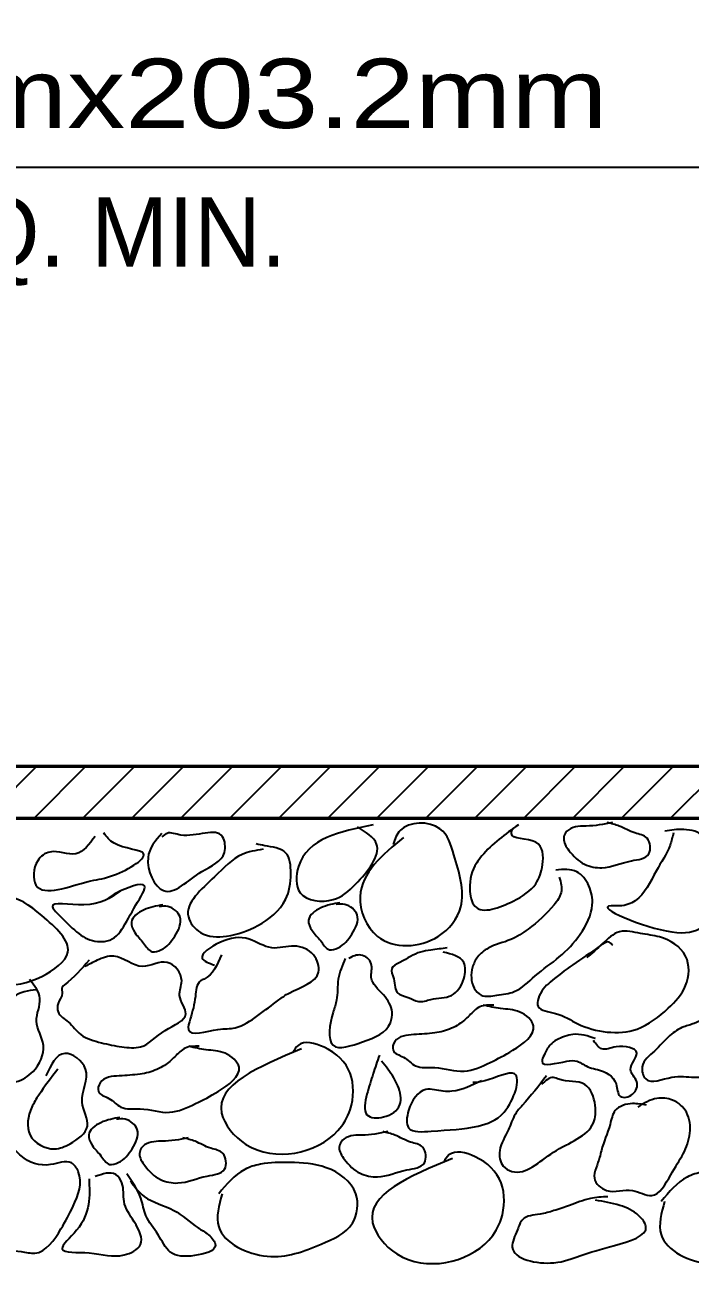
# Model space of a CAD drawing. Extents: x 442 to 1297, y -1132 to -588.
# Drawn here: x 1070.79 to 1093.84, y -929.08 to -885.89 of the extents above; entities that cross this region are included whole.
import ezdxf
from ezdxf.enums import TextEntityAlignment as Align

# ---------------------------------------------------------------- set-up
doc = ezdxf.new("R2010")
doc.units = 0
doc.header["$LTSCALE"] = 0.96
doc.layers.add('1', color=7, linetype='Continuous', lineweight=35)

msp = doc.modelspace()

# ---------------------------------------------------------------- linework, layer by layer
at = {"layer": '1'}
for p, q in [((1049.354, -890.8139), (1098.254, -890.8139)), ((1069.4082, -913.3617), (1071.2081, -911.5617)), ((1071.1053, -913.3617), (1072.9052, -911.5617)), ((1072.8024, -913.3617), (1074.6023, -911.5617)), ((1074.4994, -913.3617), (1076.2993, -911.5617)), ((1076.1964, -913.3617), (1077.9963, -911.5617)), ((1077.8934, -913.3617), (1079.6934, -911.5617)), ((1079.5904, -913.3617), (1081.3902, -911.5617)), ((1081.2874, -913.3617), (1083.0874, -911.5617)), ((1082.9844, -913.3617), (1084.7842, -911.5617)), ((1084.6815, -913.3617), (1086.4813, -911.5617)), ((1086.3784, -913.3617), (1088.1782, -911.5617)), ((1088.0755, -913.3617), (1089.8753, -911.5617)), ((1089.7724, -913.3617), (1091.5722, -911.5617)), ((1091.4695, -913.3617), (1093.2693, -911.5617)), ((1093.1664, -913.3617), (1094.9662, -911.5617))]:
    msp.add_line(p, q, dxfattribs=at)
at = {"layer": '1', "lineweight": 53}
msp.add_line((1049.354, -911.5617), (1098.254, -911.5617), dxfattribs=at)
msp.add_lwpolyline([(1047.554, -880.9617), (1047.554, -913.3617), (1100.054, -913.3617)], dxfattribs=at)
at = {"layer": '1'}
for points in [[(1073.2193, -913.9938), (1072.5576, -914.5953), (1071.6554, -914.5352), (1071.2344, -914.8359), (1071.1742, -915.678), (1072.9787, -915.5577), (1073.7606, -915.3773), (1074.9034, -914.5953), (1073.8809, -914.2344), (1073.52, -913.8735)], [(1075.5374, -913.889), (1075.0562, -914.731), (1075.5975, -915.8739), (1076.9208, -915.2122), (1077.7027, -914.5506), (1077.6426, -914.0093), (1076.199, -913.9491), (1075.7178, -913.889), (1075.5374, -914.0093)], [(1082.8568, -913.5979), (1080.2704, -915.0414), (1080.3305, -915.9437), (1081.4733, -916.1843), (1082.2553, -915.6429), (1082.9771, -914.2595), (1082.3154, -913.658)], [(1083.9092, -914.0298), (1082.4055, -916.0748), (1083.007, -917.4582), (1085.1122, -917.4582), (1085.8941, -916.4357), (1085.6535, -914.6312), (1085.1723, -913.729), (1083.7889, -913.7892), (1083.5483, -914.2703)], [(1087.8894, -913.589), (1086.6262, -914.6717), (1086.4458, -914.9123), (1086.2052, -915.8145), (1086.3856, -916.416), (1087.7089, -916.2356), (1088.4908, -915.6341), (1088.7314, -914.9724), (1088.4908, -914.1905), (1087.6488, -913.8898), (1087.7089, -913.7093)], [(1091.1468, -913.516), (1090.2445, -913.6363), (1090.1242, -913.6363), (1089.5227, -913.8769), (1089.4626, -914.0574), (1089.643, -914.4784), (1090.1844, -914.9596), (1090.7859, -915.0799), (1091.8084, -914.8393), (1092.4099, -914.5987), (1092.3497, -914.0574), (1091.9287, -913.8769), (1091.3873, -913.6363), (1090.9663, -913.516)], [(1093.2663, -913.8754), (1093.146, -914.2964), (1092.6648, -915.1986), (1091.943, -916.2212), (1091.4017, -916.4016), (1091.1009, -916.4016), (1093.2061, -917.3039), (1094.2888, -917.1234), (1094.8903, -916.4618), (1095.0707, -915.5595), (1094.5294, -914.8378), (1094.2888, -913.9957), (1093.6272, -913.7551), (1092.9655, -913.8152)], [(1079.0421, -914.438), (1078.3203, -914.6184), (1077.3579, -915.4003), (1076.4557, -916.7838), (1076.8767, -917.3251), (1077.7789, -917.4454), (1078.8616, -917.0845), (1079.824, -916.1823), (1080.0044, -915.28), (1079.824, -914.5583), (1079.1022, -914.3177), (1078.8015, -914.2575)], [(1089.3095, -915.4008), (1089.3697, -915.9421), (1089.1291, -916.3631), (1088.2268, -917.2052), (1087.6254, -917.5661), (1086.8434, -917.8669), (1086.4825, -918.1676), (1086.3021, -918.5285), (1086.3622, -919.2503), (1086.6028, -919.4909), (1087.1442, -919.4909), (1087.7456, -919.3706), (1088.4674, -918.8292), (1089.3095, -918.1676), (1090.0313, -917.3857), (1090.4523, -916.3631), (1090.332, -915.7015), (1089.911, -915.2203), (1089.1892, -915.1602)], [(1074.0914, -915.8887), (1072.8283, -916.3699), (1071.7456, -916.4301), (1072.0463, -916.791), (1073.3095, -917.633), (1073.5501, -917.633), (1074.6327, -916.3699), (1074.9335, -915.7083), (1073.9711, -915.9489), (1073.6704, -916.1293)], [(1069.6315, -916.6184), (1068.8496, -917.5807), (1068.9098, -918.3627), (1069.9323, -919.0845), (1071.3759, -918.8439), (1072.2781, -918.0018), (1071.3759, -916.7387), (1070.1729, -916.1372), (1069.391, -916.7988)], [(1075.5653, -916.3647), (1074.9037, -916.5452), (1074.4827, -916.9662), (1074.603, -917.3271), (1074.9037, -917.688), (1075.2044, -917.9888), (1075.5052, -917.9286), (1075.9864, -917.4474), (1076.1668, -916.7858), (1075.7458, -916.4249), (1075.445, -916.4249)], [(1081.7019, -916.2934), (1081.0403, -916.4739), (1080.6193, -916.8949), (1080.7396, -917.2558), (1081.0403, -917.6167), (1081.341, -917.9175), (1081.6418, -917.8573), (1082.123, -917.3761), (1082.3034, -916.7145), (1081.8824, -916.3536), (1081.5816, -916.3536)], [(1091.1597, -917.7784), (1091.0394, -917.6581), (1090.7386, -917.7784), (1089.7763, -918.44), (1088.9943, -919.0415), (1088.7537, -919.2821), (1088.5733, -919.8836), (1089.1748, -920.1242), (1089.9567, -920.4851), (1092.0018, -920.6655), (1093.0844, -919.9437), (1093.6859, -919.1618), (1093.6859, -918.1393), (1092.7837, -917.4776), (1092.1221, -917.3574), (1091.4003, -917.2972), (1090.7988, -917.7182), (1090.2574, -918.1994)], [(1077.5997, -918.0949), (1076.9982, -918.937), (1076.8779, -918.9972), (1076.6975, -919.5385), (1076.517, -920.3204), (1076.4569, -920.6813), (1077.4794, -920.6813), (1078.0809, -920.6212), (1078.8628, -920.2001), (1079.5846, -919.6588), (1079.9455, -919.4182), (1080.9681, -918.6964), (1080.7876, -918.0949), (1080.126, -917.7942), (1079.344, -917.8543), (1078.5621, -917.5536), (1077.5396, -917.6739), (1076.9381, -918.2152), (1077.3591, -918.4558)], [(1073.0116, -918.2858), (1072.1553, -919.1421), (1072.084, -919.2134), (1072.084, -919.4275), (1071.9413, -919.7843), (1071.9413, -920.0697), (1072.298, -920.4265), (1072.7262, -920.8546), (1073.4397, -921.14), (1074.1533, -921.2828), (1074.7955, -921.2828), (1075.6517, -920.7119), (1076.3653, -920.1411), (1076.1512, -919.4989), (1076.2226, -918.9994), (1075.7231, -918.3572), (1074.8668, -918.4999), (1073.8678, -918.1431), (1073.297, -918.2858), (1072.8689, -918.4999)], [(1081.8905, -918.2224), (1081.6499, -918.9441), (1081.5897, -919.6659), (1081.4694, -920.087), (1081.4694, -921.2298), (1082.492, -921.1095), (1083.4543, -920.4479), (1083.5145, -920.087), (1083.2137, -919.4855), (1082.7927, -918.884), (1082.7927, -918.4028), (1082.4318, -918.1021), (1082.0108, -918.2224)], [(1085.4274, -917.8577), (1084.8566, -917.9291), (1084.4998, -918.0004), (1083.7862, -918.3572), (1083.5008, -918.5713), (1083.5722, -918.928), (1083.7149, -919.4275), (1084.0717, -919.5702), (1084.4284, -919.7129), (1084.8566, -919.6416), (1085.5701, -919.4989), (1085.9982, -918.928), (1085.9982, -918.3572), (1085.2847, -918.0004)], [(1071.1916, -919.3087), (1070.4097, -919.5493), (1070.1691, -920.0305), (1069.9285, -920.7522), (1069.5676, -920.8725), (1069.3871, -921.5342), (1069.5676, -922.4364), (1070.4698, -922.4966), (1071.0713, -922.1357), (1071.4322, -921.2334), (1071.1916, -920.3913), (1071.3119, -919.6094), (1070.951, -918.9478)], [(1087.0359, -919.8369), (1086.5547, -919.8971), (1086.1939, -920.1978), (1085.833, -920.4986), (1085.2916, -920.7391), (1084.9909, -920.7993), (1084.2691, -920.8594), (1083.6075, -921.1), (1083.5473, -921.4008), (1083.9082, -921.6414), (1084.3292, -921.9421), (1084.9909, -922.0023), (1086.0134, -922.1226), (1086.9156, -921.8218), (1087.6976, -921.4008), (1088.4194, -920.5587), (1087.9382, -920.0775), (1087.2765, -919.9572), (1086.675, -919.8369)], [(1094.5878, -920.2892), (1094.287, -920.3494), (1093.9863, -920.4697), (1093.8059, -920.5298), (1093.6254, -920.59), (1093.1442, -920.8907), (1092.6029, -921.4321), (1092.1818, -921.9734), (1092.3021, -922.3945), (1093.2044, -922.3343), (1093.9863, -922.3343), (1094.9487, -922.214), (1095.6705, -921.8531), (1095.7306, -921.2516), (1095.4299, -920.6501), (1094.5878, -920.3494), (1094.287, -920.2291)], [(1080.3754, -921.3539), (1077.6085, -923.5794), (1078.4506, -924.662), (1081.6385, -924.1809), (1082.0595, -923.4591), (1082.0595, -922.1959), (1081.1573, -921.2937), (1080.2551, -921.2336), (1080.0746, -921.4742)], [(1090.565, -920.9973), (1089.7801, -920.8546), (1089.4947, -920.926), (1088.9952, -921.2114), (1088.7811, -921.5682), (1088.7097, -921.7822), (1089.566, -921.7822), (1089.9228, -921.7822), (1090.3509, -921.9963), (1090.6363, -922.0677), (1091.2785, -922.5671), (1091.4212, -922.9953), (1091.8494, -922.9239), (1091.9921, -922.4958), (1091.778, -922.0677), (1091.9921, -921.4968), (1091.2785, -921.2828), (1090.7791, -921.3541), (1090.4936, -921.0687)], [(1071.9322, -922.0504), (1071.2706, -922.9526), (1071.03, -923.3737), (1070.9699, -924.336), (1071.8119, -924.8172), (1072.3533, -924.6368), (1072.9548, -924.0353), (1072.7743, -923.1932), (1072.8946, -922.0504), (1072.1728, -921.5091), (1071.5112, -922.291)], [(1076.8266, -921.2641), (1076.3454, -921.3243), (1075.9846, -921.625), (1075.6237, -921.9258), (1075.0823, -922.1663), (1074.7816, -922.2265), (1074.0598, -922.2866), (1073.3982, -922.5272), (1073.338, -922.828), (1073.6989, -923.0686), (1074.1199, -923.3693), (1074.7816, -923.4295), (1075.8041, -923.5498), (1076.7063, -923.249), (1077.4883, -922.828), (1078.2101, -921.9859), (1077.7289, -921.5047), (1077.0672, -921.3844), (1076.4657, -921.2641)], [(1083.0727, -921.5682), (1082.8586, -922.2104), (1082.6445, -922.9239), (1082.6445, -923.6375), (1083.2154, -923.7088), (1083.7862, -923.2807), (1083.7149, -922.6385), (1083.5722, -922.3531), (1083.144, -921.7822)], [(1086.613, -922.4608), (1085.5905, -922.8217), (1085.2897, -922.8217), (1084.6882, -922.7615), (1084.0868, -923.4833), (1084.0868, -924.0848), (1084.8687, -924.2051), (1086.4927, -924.0247), (1087.3949, -923.5435), (1087.7558, -922.2202), (1086.7333, -922.4608), (1086.3123, -922.5209)], [(1088.8692, -922.2862), (1088.0271, -923.3088), (1087.7865, -923.6095), (1087.5459, -924.1508), (1087.2452, -924.8726), (1087.3655, -925.414), (1087.6662, -925.5944), (1089.1098, -924.9328), (1090.4932, -923.9102), (1090.5534, -923.3088), (1090.1925, -922.587), (1089.2902, -922.4065), (1089.1098, -922.3464), (1088.6887, -922.587)], [(1092.3304, -923.308), (1091.8492, -923.2479), (1091.2478, -923.4884), (1091.0673, -923.9696), (1090.7666, -924.8719), (1090.7064, -925.1125), (1090.5861, -925.4734), (1090.526, -925.8342), (1090.947, -926.2553), (1091.8492, -926.2553), (1092.5109, -926.4357), (1093.1725, -925.714), (1093.8342, -924.2704), (1093.7139, -923.5486), (1093.2327, -923.1276), (1092.6913, -923.0674), (1092.0297, -923.3681)], [(1074.0834, -923.7293), (1073.4218, -923.9098), (1073.0008, -924.3308), (1073.1211, -924.6917), (1073.4218, -925.0526), (1073.7225, -925.3534), (1074.0233, -925.2932), (1074.5045, -924.812), (1074.6849, -924.1504), (1074.2639, -923.7895), (1073.9631, -923.7895)], [(1083.369, -924.2193), (1082.4667, -924.3396), (1082.3464, -924.3396), (1081.7449, -924.5802), (1081.6848, -924.7607), (1081.8652, -925.1817), (1082.4066, -925.6629), (1083.0081, -925.7832), (1084.0306, -925.5426), (1084.6321, -925.302), (1084.5719, -924.7607), (1084.1509, -924.5802), (1083.6095, -924.3396), (1083.1885, -924.2193)], [(1076.4476, -924.4334), (1075.5453, -924.5537), (1075.425, -924.5537), (1074.8235, -924.7943), (1074.7634, -924.9748), (1074.9438, -925.3958), (1075.4852, -925.877), (1076.0867, -925.9973), (1077.1092, -925.7567), (1077.7107, -925.5161), (1077.6505, -924.9748), (1077.2295, -924.7943), (1076.6881, -924.5537), (1076.2671, -924.4334)], [(1070.4153, -924.8806), (1070.1145, -925.1212), (1069.9942, -925.3618), (1069.4529, -926.2641), (1069.092, -926.8054), (1068.9115, -927.046), (1068.1898, -927.8279), (1068.1296, -928.3091), (1069.1521, -928.3693), (1069.8138, -928.3693), (1070.6559, -928.3693), (1071.137, -928.4294), (1072.0393, -927.5873), (1072.4603, -926.8054), (1072.6408, -925.6024), (1072.4002, -925.3017), (1071.6784, -925.3618), (1070.6559, -925.0611), (1070.4754, -924.8806)], [(1085.6061, -925.1466), (1082.8392, -927.3721), (1083.6813, -928.4547), (1086.8692, -927.9736), (1087.2902, -927.2518), (1087.2902, -925.9886), (1086.388, -925.0864), (1085.4858, -925.0263), (1085.3053, -925.2669)], [(1077.626, -926.371), (1077.5057, -927.5138), (1079.1899, -928.5364), (1081.0545, -928.1153), (1082.1372, -927.3935), (1082.2575, -926.371), (1081.235, -925.4688), (1079.9718, -925.2883), (1078.9493, -925.3485), (1078.408, -925.5289), (1077.5057, -926.371)], [(1092.9579, -926.6357), (1092.8376, -927.7785), (1094.5218, -928.8011), (1096.3864, -928.38), (1097.4691, -927.6582), (1097.5894, -926.6357), (1096.5669, -925.7335), (1095.3037, -925.553), (1094.2812, -925.6132), (1093.7399, -925.7936), (1092.8376, -926.6357)], [(1073.0116, -925.8495), (1072.5834, -927.6334), (1072.084, -928.2756), (1073.0116, -928.4183), (1074.2246, -928.4896), (1074.7955, -928.1329), (1074.5814, -927.348), (1074.2246, -926.6344), (1074.1533, -925.9922), (1073.9392, -925.7068), (1073.2256, -925.7781)], [(1074.4447, -925.9246), (1074.9259, -926.466), (1075.9484, -926.9471), (1076.7905, -927.5486), (1077.1514, -927.7892), (1077.392, -928.1501), (1076.6702, -928.511), (1075.8281, -928.3907), (1075.4071, -927.7892), (1074.9861, -927.1276), (1074.8056, -926.5261), (1074.3244, -925.684)], [(1090.9869, -926.4747), (1090.3855, -926.5348), (1089.6637, -926.7754), (1089.1223, -926.9558), (1088.6411, -927.0761), (1088.0397, -927.2566), (1087.8592, -927.6175), (1087.6788, -928.219), (1089.1223, -928.7603), (1090.0246, -928.5197), (1091.2275, -928.1588), (1092.3102, -927.4972), (1092.0696, -927.1363), (1091.408, -926.7754), (1090.5659, -926.595)]]:
    msp.add_spline(points, degree=3, dxfattribs=at)

# ---------------------------------------------------------------- texts
at = {"layer": '1', "width": 1.25}
msp.add_text('203.2mmx203.2mm', height=2.4, dxfattribs=at).set_placement((1073.2604, -889.4616), align=Align.CENTER)
at = {"layer": '1'}
msp.add_text('SQ. MIN.', height=2.4, dxfattribs=at).set_placement((1073.2604, -894.2616), align=Align.CENTER)

doc.saveas('drawing.dxf')
